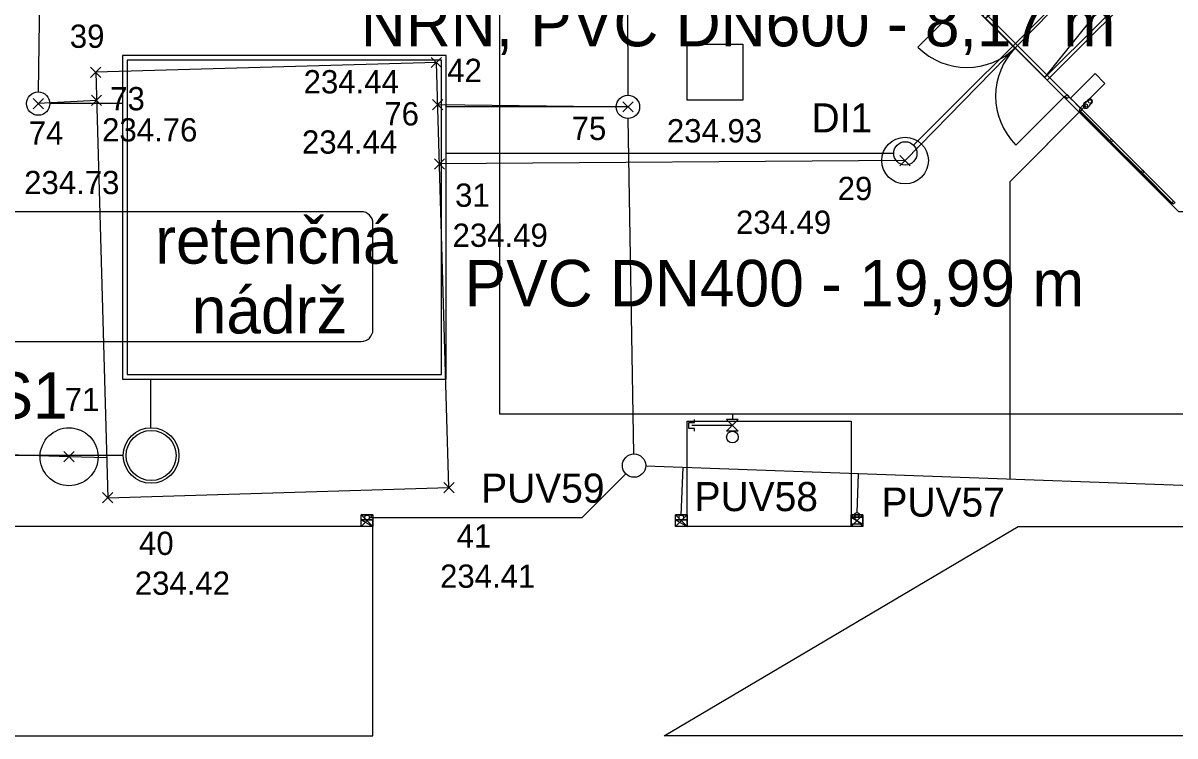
# Model space of a CAD drawing. Extents: x -264234 to -263604, y -1242346 to -1242049.
# Drawn here: x -263944.61 to -263895.14, y -1242263.98 to -1242233.35 of the extents above; entities that cross this region are included whole.
import ezdxf

# ---------------------------------------------------------------- set-up
doc = ezdxf.new("R2010")
doc.units = 0
for name, color, linetype in [('KFA_BODY_CISLO', 7, 'Continuous'), ('KFA_BODY_SYMBOL', 7, 'Continuous'), ('KFA_BODY_VYSKA', 7, 'Continuous'), ('KFA_DAZDOVA_KANALIZACIA_retencna_nadrz', 7, 'Continuous'), ('KFA_DAZDOVA_KANALIZACIA_retencna_nadrz_popis', 7, 'Continuous'), ('KFA_DAZDOVA_KANALIZACIA_vetva_I', 7, 'Continuous'), ('KFA_DAZDOVA_KANALIZACIA_vetva_I_popis', 7, 'Continuous'), ('KFA_JESTV_IS_DSP_-_KANAL_DAZD', 7, 'Continuous'), ('KFA_SITUACIA_DSP', 7, 'Continuous'), ('KFA_SO_40-2-II_DK_PRIPOJKY_UV_PROJEKT', 7, 'Continuous'), ('KFA_SO_40-2-II_DK_PRIPOJKY_UV_PROJEKT_popis', 7, 'Continuous'), ('KFA_SO_40-2-II_DK_UV_PROJEKT', 7, 'Continuous')]:
    doc.layers.add(name, color=color, linetype=linetype)

msp = doc.modelspace()

# ---------------------------------------------------------------- linework, layer by layer
at = {"layer": 'KFA_BODY_SYMBOL'}
for p, q in [((-263927.075, -1242235.264), (-263926.633, -1242234.822)), ((-263926.633, -1242235.264), (-263927.075, -1242234.822)), ((-263941.707, -1242235.684), (-263941.265, -1242235.242)), ((-263941.265, -1242235.684), (-263941.707, -1242235.242)), ((-263944.175, -1242237.032), (-263943.733, -1242236.59)), ((-263943.733, -1242237.032), (-263944.175, -1242236.59)), ((-263941.673, -1242236.893), (-263941.231, -1242236.451)), ((-263941.231, -1242236.893), (-263941.673, -1242236.451)), ((-263927.022, -1242237.075), (-263926.58, -1242236.633)), ((-263926.58, -1242237.075), (-263927.022, -1242236.633)), ((-263918.851, -1242237.17), (-263918.409, -1242236.728)), ((-263918.409, -1242237.17), (-263918.851, -1242236.728)), ((-263926.944, -1242239.621), (-263926.502, -1242239.179)), ((-263926.502, -1242239.621), (-263926.944, -1242239.179)), ((-263906.952, -1242239.48), (-263906.51, -1242239.038)), ((-263906.51, -1242239.48), (-263906.952, -1242239.038)), ((-263942.851, -1242252.206), (-263942.409, -1242251.764)), ((-263942.409, -1242252.206), (-263942.851, -1242251.764)), ((-263926.538, -1242253.53), (-263926.096, -1242253.088)), ((-263926.096, -1242253.53), (-263926.538, -1242253.088)), ((-263941.19, -1242253.97), (-263940.748, -1242253.528)), ((-263940.748, -1242253.97), (-263941.19, -1242253.528))]:
    msp.add_line(p, q, dxfattribs=at)
at = {"layer": 'KFA_DAZDOVA_KANALIZACIA_retencna_nadrz'}
for p, q in [((-263941.452, -1242236.672), (-263943.954, -1242236.811)), ((-263926.801, -1242236.854), (-263918.63, -1242236.949))]:
    msp.add_line(p, q, dxfattribs=at)
msp.add_lwpolyline([(-263941.486, -1242235.463), (-263940.969, -1242253.749), (-263926.317, -1242253.309), (-263926.854, -1242235.043)], close=True, dxfattribs=at)
msp.add_lwpolyline([(-263941.017, -1242252.038), (-263942.63, -1242251.985), (-263956.104, -1242251.541)], dxfattribs=at)
msp.add_ellipse((-263942.63, -1242251.985), major_axis=(-0.489, -1.145), ratio=0.999966, dxfattribs=at)
at = {"layer": 'KFA_DAZDOVA_KANALIZACIA_vetva_I'}
msp.add_line((-263906.731, -1242239.259), (-263926.723, -1242239.4), dxfattribs=at)
msp.add_lwpolyline([(-263814.907, -1242107.856), (-263815.198, -1242164.443), (-263815.189, -1242220.791), (-263852.152, -1242220.736), (-263888.701, -1242220.786), (-263906.731, -1242239.259)], dxfattribs=at)
msp.add_circle((-263906.731, -1242239.259), 1, dxfattribs=at)
at = {"layer": 'KFA_JESTV_IS_DSP_-_KANAL_DAZD'}
for p, q in [((-263943.946, -1242236.311), (-263943.136, -1242185.245)), ((-263918.755, -1242197.225), (-263918.632, -1242236.449)), ((-263918.378, -1242251.867), (-263918.622, -1242237.449)), ((-263891.022, -1242253.354), (-263917.87, -1242252.385))]:
    msp.add_line(p, q, dxfattribs=at)
for centre in [(-263918.63, -1242236.949), (-263918.369, -1242252.367)]:
    msp.add_circle(centre, 0.5, dxfattribs=at)
at = {"layer": 'KFA_SITUACIA_DSP'}
for p, q in [((-263924.143, -1242185.14), (-263924.143, -1242250.14)), ((-263889.023, -1242221.253), (-263906.365, -1242238.596)), ((-263908.663, -1242227.55), (-263895.135, -1242241.078)), ((-263904.074, -1242232.281), (-263906.177, -1242234.384)), ((-263916.093, -1242234.257), (-263913.693, -1242234.257)), ((-263916.093, -1242236.657), (-263916.093, -1242234.257)), ((-263913.693, -1242234.257), (-263913.693, -1242236.657)), ((-263926.43, -1242234.749), (-263940.33, -1242234.749)), ((-263940.33, -1242234.749), (-263940.33, -1242248.649)), ((-263926.43, -1242248.649), (-263926.43, -1242234.749)), ((-263926.63, -1242234.949), (-263940.13, -1242234.949)), ((-263940.13, -1242234.949), (-263940.13, -1242248.449)), ((-263926.63, -1242248.449), (-263926.63, -1242234.949)), ((-263899.631, -1242236.576), (-263898.571, -1242235.516)), ((-263898.571, -1242235.516), (-263898.147, -1242235.94)), ((-263898.147, -1242235.94), (-263899.207, -1242237.001)), ((-263940.33, -1242236.811), (-263943.454, -1242236.811)), ((-263913.693, -1242236.657), (-263916.093, -1242236.657)), ((-263899.866, -1242236.488), (-263901.97, -1242238.592)), ((-263899.849, -1242236.506), (-263899.764, -1242236.421)), ((-263899.764, -1242236.591), (-263899.849, -1242236.506)), ((-263899.764, -1242236.421), (-263899.679, -1242236.506)), ((-263899.679, -1242236.506), (-263899.764, -1242236.591)), ((-263899.207, -1242237.001), (-263899.631, -1242236.576)), ((-263898.969, -1242236.733), (-263899.047, -1242236.812)), ((-263898.949, -1242236.733), (-263898.969, -1242236.733)), ((-263898.861, -1242236.645), (-263898.949, -1242236.733)), ((-263898.715, -1242236.791), (-263898.804, -1242236.879)), ((-263918.63, -1242236.949), (-263926.43, -1242236.949)), ((-263898.965, -1242236.895), (-263902.238, -1242240.168)), ((-263899.018, -1242236.948), (-263902.238, -1242240.168)), ((-263899.185, -1242237.014), (-263899.255, -1242237.084)), ((-263899.255, -1242237.084), (-263899.227, -1242237.113)), ((-263899.232, -1242237.108), (-263899.25, -1242237.125)), ((-263899.25, -1242237.125), (-263897.942, -1242238.434)), ((-263897.924, -1242238.416), (-263899.232, -1242237.108)), ((-263899.227, -1242237.113), (-263899.199, -1242237.141)), ((-263899.199, -1242237.141), (-263899.128, -1242237.07)), ((-263899.128, -1242237.07), (-263899.185, -1242237.014)), ((-263898.804, -1242236.899), (-263898.882, -1242236.977)), ((-263898.882, -1242236.977), (-263898.804, -1242236.899)), ((-263898.804, -1242236.879), (-263898.804, -1242236.899)), ((-263897.865, -1242238.333), (-263897.936, -1242238.404)), ((-263897.809, -1242238.389), (-263897.865, -1242238.333)), ((-263897.942, -1242238.434), (-263897.924, -1242238.416)), ((-263897.936, -1242238.404), (-263897.908, -1242238.432)), ((-263897.908, -1242238.432), (-263897.88, -1242238.46)), ((-263897.888, -1242238.452), (-263897.906, -1242238.469)), ((-263897.906, -1242238.469), (-263896.598, -1242239.778)), ((-263896.58, -1242239.76), (-263897.888, -1242238.452)), ((-263897.88, -1242238.46), (-263897.809, -1242238.389)), ((-263907.219, -1242238.949), (-263926.43, -1242238.949)), ((-263896.598, -1242239.778), (-263896.58, -1242239.76)), ((-263896.522, -1242239.677), (-263896.592, -1242239.748)), ((-263896.592, -1242239.748), (-263896.564, -1242239.776)), ((-263896.566, -1242239.809), (-263896.548, -1242239.792)), ((-263895.258, -1242241.118), (-263896.566, -1242239.809)), ((-263896.564, -1242239.776), (-263896.536, -1242239.804)), ((-263896.548, -1242239.792), (-263895.24, -1242241.1)), ((-263896.536, -1242239.804), (-263896.465, -1242239.733)), ((-263896.465, -1242239.733), (-263896.522, -1242239.677)), ((-263902.238, -1242240.168), (-263902.238, -1242252.949)), ((-263895.202, -1242240.996), (-263895.273, -1242241.067)), ((-263895.273, -1242241.067), (-263895.245, -1242241.095)), ((-263895.24, -1242241.1), (-263895.258, -1242241.118)), ((-263895.245, -1242241.095), (-263895.216, -1242241.123)), ((-263895.216, -1242241.123), (-263895.146, -1242241.053)), ((-263895.146, -1242241.053), (-263895.202, -1242240.996)), ((-263930.081, -1242241.458), (-263948.093, -1242241.458)), ((-263929.582, -1242246.53), (-263929.581, -1242241.959)), ((-263953.119, -1242247.03), (-263930.082, -1242247.03)), ((-263940.33, -1242248.649), (-263926.43, -1242248.649)), ((-263940.13, -1242248.449), (-263926.63, -1242248.449)), ((-263939.13, -1242248.649), (-263939.13, -1242250.737)), ((-263924.143, -1242250.14), (-263788.143, -1242250.14)), ((-263914.143, -1242250.14), (-263914.143, -1242250.39)), ((-263914.143, -1242250.14), (-263914.143, -1242250.39)), ((-263916.093, -1242254.982), (-263916.093, -1242250.458)), ((-263916.093, -1242250.458), (-263909.043, -1242250.458)), ((-263916.018, -1242250.515), (-263915.768, -1242250.515)), ((-263916.018, -1242250.765), (-263916.018, -1242250.515)), ((-263914.143, -1242250.64), (-263915.893, -1242250.64)), ((-263915.768, -1242250.515), (-263915.768, -1242250.39)), ((-263914.393, -1242250.39), (-263913.893, -1242250.89)), ((-263913.893, -1242250.39), (-263914.393, -1242250.39)), ((-263914.393, -1242250.89), (-263913.893, -1242250.39)), ((-263909.043, -1242250.458), (-263909.043, -1242254.982)), ((-263915.768, -1242250.765), (-263916.018, -1242250.765)), ((-263915.768, -1242250.89), (-263915.768, -1242250.765)), ((-263913.893, -1242250.89), (-263914.393, -1242250.89)), ((-263940.302, -1242251.932), (-263951.5, -1242251.932)), ((-263916.339, -1242254.492), (-263916.265, -1242252.443)), ((-263920.595, -1242254.592), (-263918.723, -1242252.72)), ((-263908.789, -1242254.387), (-263908.729, -1242252.715)), ((-263929.73, -1242254.592), (-263920.595, -1242254.592)), ((-263909.043, -1242254.587), (-263908.543, -1242254.587)), ((-263909.043, -1242254.877), (-263909.043, -1242254.587)), ((-263909.043, -1242254.587), (-263908.543, -1242254.877)), ((-263909.043, -1242254.587), (-263908.543, -1242254.877)), ((-263908.543, -1242254.587), (-263909.043, -1242254.587)), ((-263908.543, -1242254.587), (-263908.543, -1242254.877)), ((-263908.543, -1242254.877), (-263908.543, -1242254.587)), ((-263930.08, -1242254.692), (-263929.58, -1242254.692)), ((-263930.08, -1242254.982), (-263930.08, -1242254.692)), ((-263930.08, -1242254.692), (-263929.58, -1242254.982)), ((-263930.08, -1242254.692), (-263929.58, -1242254.982)), ((-263929.58, -1242254.692), (-263930.08, -1242254.692)), ((-263929.58, -1242254.982), (-263930.08, -1242254.982)), ((-263929.58, -1242254.692), (-263929.58, -1242254.982)), ((-263929.58, -1242254.982), (-263929.58, -1242254.692)), ((-263916.593, -1242254.692), (-263916.093, -1242254.692)), ((-263916.593, -1242254.982), (-263916.593, -1242254.692)), ((-263916.593, -1242254.692), (-263916.093, -1242254.982)), ((-263916.593, -1242254.692), (-263916.093, -1242254.982)), ((-263916.093, -1242254.692), (-263916.593, -1242254.692)), ((-263916.093, -1242254.982), (-263916.593, -1242254.982)), ((-263916.093, -1242254.692), (-263916.093, -1242254.982)), ((-263916.093, -1242254.982), (-263916.093, -1242254.692)), ((-263909.043, -1242254.982), (-263916.093, -1242254.982)), ((-263908.543, -1242254.877), (-263909.043, -1242254.877))]:
    msp.add_line(p, q, dxfattribs=at)
for points in [[(-263794.893, -1242227.382), (-263808.968, -1242241.457), (-263894.968, -1242241.457), (-263909.043, -1242227.382), (-263909.043, -1242196.333), (-263914.143, -1242196.333), (-263914.143, -1242132.433), (-263909.043, -1242132.433), (-263909.043, -1242101.382), (-263894.968, -1242087.307), (-263808.968, -1242087.307), (-263794.893, -1242101.382), (-263794.893, -1242227.382)], [(-263903.277, -1242233.148), (-263900.731, -1242235.694), (-263890.333, -1242222.748), (-263903.277, -1242233.148)], [(-263898.65, -1242228.301), (-263903.39, -1242233.035), (-263900.629, -1242235.796), (-263895.875, -1242231.049)], [(-263898.544, -1242228.407), (-263903.281, -1242233.144), (-263900.731, -1242235.694), (-263895.982, -1242230.943)], [(-263929.58, -1242254.982), (-263970.077, -1242254.982), (-263970.077, -1242263.982), (-263929.58, -1242263.982), (-263929.58, -1242254.982)], [(-263854.468, -1242263.985), (-263917.08, -1242263.982), (-263901.868, -1242254.982), (-263854.468, -1242254.985), (-263854.468, -1242263.985)]]:
    msp.add_lwpolyline(points, dxfattribs=at)
for centre, radius in [((-263943.954, -1242236.811), 0.5), ((-263918.63, -1242236.949), 0.5), ((-263898.965, -1242236.895), 0.075), ((-263898.788, -1242236.718), 0.075), ((-263906.719, -1242238.949), 0.5), ((-263939.107, -1242251.932), 1.195), ((-263939.107, -1242251.932), 1.075), ((-263914.143, -1242251.14), 0.25), ((-263929.83, -1242254.592), 0.1), ((-263916.343, -1242254.592), 0.1), ((-263908.793, -1242254.487), 0.1)]:
    msp.add_circle(centre, radius, dxfattribs=at)
for centre, radius, start, end in [((-263904.074, -1242232.281), 2.975, 225.0001, 315.0001), ((-263899.866, -1242236.488), 2.975, 134.9999, 224.9999), ((-263898.965, -1242236.895), 0.117, 135, 315), ((-263898.788, -1242236.718), 0.103, 315, 135), ((-263930.081, -1242241.958), 0.5, 359.9785, 89.9999), ((-263930.082, -1242246.53), 0.5, 270, 359.9785)]:
    msp.add_arc(centre, radius, start, end, dxfattribs=at)
at = {"layer": 'KFA_SO_40-2-II_DK_PRIPOJKY_UV_PROJEKT'}
for points in [[(-263916.339, -1242254.492), (-263916.265, -1242252.443)], [(-263929.73, -1242254.592), (-263920.595, -1242254.592), (-263918.723, -1242252.72)], [(-263908.789, -1242254.387), (-263908.729, -1242252.715)]]:
    msp.add_lwpolyline(points, dxfattribs=at)
at = {"layer": 'KFA_SO_40-2-II_DK_UV_PROJEKT'}
for points in [[(-263930.08, -1242254.982), (-263930.08, -1242254.482), (-263929.58, -1242254.482), (-263929.58, -1242254.982), (-263930.08, -1242254.982), (-263929.58, -1242254.482), (-263930.08, -1242254.482), (-263929.58, -1242254.982)], [(-263916.593, -1242254.982), (-263916.593, -1242254.482), (-263916.093, -1242254.482), (-263916.093, -1242254.982), (-263916.593, -1242254.982), (-263916.093, -1242254.482), (-263916.593, -1242254.482), (-263916.093, -1242254.982)], [(-263909.043, -1242254.982), (-263909.043, -1242254.482), (-263908.543, -1242254.482), (-263908.543, -1242254.982), (-263909.043, -1242254.982), (-263908.543, -1242254.482), (-263909.043, -1242254.482), (-263908.543, -1242254.982)]]:
    msp.add_lwpolyline(points, dxfattribs=at)

# ---------------------------------------------------------------- texts
at = {"layer": 'KFA_BODY_CISLO'}
for s, p in [('39', (-263942.597, -1242234.414)), ('42', (-263926.392, -1242235.883)), ('73', (-263940.864, -1242237.098)), ('76', (-263929.092, -1242237.748)), ('74', (-263944.36, -1242238.571)), ('75', (-263921.047, -1242238.375)), ('31', (-263926.052, -1242241.244)), ('29', (-263909.624, -1242240.957)), ('71', (-263942.815, -1242250.024)), ('41', (-263925.985, -1242255.893)), ('40', (-263939.627, -1242256.206))]:
    msp.add_text(s, height=1, dxfattribs=at).set_placement(p)
at = {"layer": 'KFA_BODY_VYSKA'}
for s, p in [('234.44', (-263932.557, -1242236.371)), ('234.76', (-263941.21, -1242238.437)), ('234.93', (-263916.958, -1242238.477)), ('234.44', (-263932.629, -1242238.961)), ('234.73', (-263944.558, -1242240.701)), ('234.49', (-263913.993, -1242242.408)), ('234.49', (-263926.162, -1242242.966)), ('234.41', (-263926.698, -1242257.616)), ('234.42', (-263939.807, -1242257.917))]:
    msp.add_text(s, height=1, dxfattribs=at).set_placement(p)
at = {"layer": 'KFA_DAZDOVA_KANALIZACIA_retencna_nadrz_popis'}
for s, p in [('NRN, PVC DN600 - 8,17 m', (-263930.102, -1242234.349)), ('retenčná', (-263938.93, -1242243.687)), ('nádrž', (-263937.362, -1242246.687)), ('ČS1', (-263947.89, -1242250.351))]:
    msp.add_text(s, height=2, dxfattribs=at).set_placement(p)
at = {"layer": 'KFA_DAZDOVA_KANALIZACIA_vetva_I_popis'}
for s, height, p in [('DI1', 1.25, (-263910.746, -1242238.047)), ('PVC DN400 - 19,99 m', 2, (-263925.643, -1242245.525))]:
    msp.add_text(s, height=height, dxfattribs=at).set_placement(p)
at = {"layer": 'KFA_SO_40-2-II_DK_PRIPOJKY_UV_PROJEKT_popis'}
for s, p in [('PUV59', (-263924.932, -1242253.959)), ('PUV58', (-263915.768, -1242254.322)), ('PUV57', (-263907.743, -1242254.558))]:
    msp.add_text(s, height=1.25, dxfattribs=at).set_placement(p)

doc.saveas('drawing.dxf')
